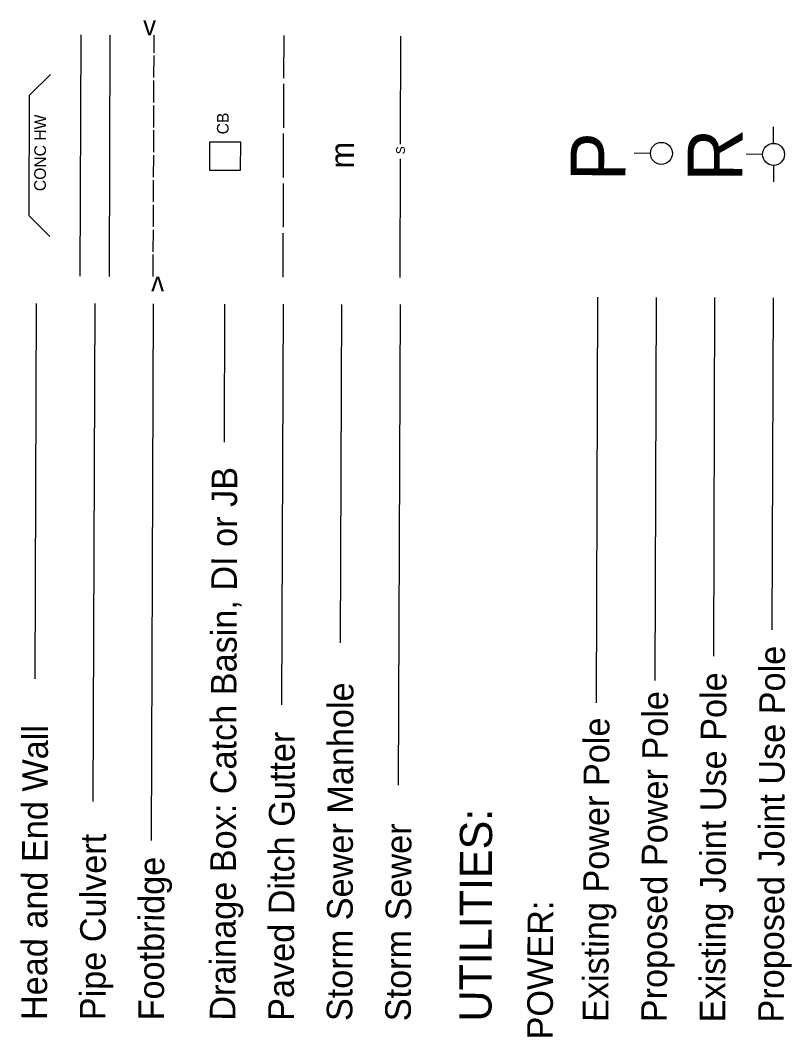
# Model space of a CAD drawing. Extents: x 2364794 to 2387902, y 795230 to 810426.
# Drawn here: x 2374608 to 2376455, y 805109 to 807541 of the extents above; entities that cross this region are included whole.
import ezdxf

# ---------------------------------------------------------------- set-up
doc = ezdxf.new("R2010")
doc.units = 0
doc.layers.add('Old_Level_5', color=7, linetype='Continuous')
doc.layers.add('Old_Level_63', color=7, linetype='Continuous')

# ---------------------------------------------------------------- blocks, each defined once
blk = doc.blocks.new('POLE')
at = {"layer": 'Old_Level_63'}
blk.add_line((0, 0.05), (0, 0.125), dxfattribs=at)
blk.add_circle((0, 0), 0.05, dxfattribs=at)
blk = doc.blocks.new('POLE4')
at = {"layer": 'Old_Level_63'}
for p, q in [((0, 0.0502), (0, 0.1252)), ((-0.05, 0.0002), (-0.125, 0.0002)), ((0.05, 0.0002), (0.125, 0.0002))]:
    blk.add_line(p, q, dxfattribs=at)
blk.add_circle((0, 0), 0.05, dxfattribs=at)

msp = doc.modelspace()

# ---------------------------------------------------------------- linework, layer by layer
at = {"layer": 'Old_Level_63'}
for p, q in [((2374751.3, 806928.4), (2374753.4, 807505.9)), ((2374821.3, 806928.1), (2374823.4, 807505.6)), ((2374928.2, 807463.2), (2374928.4, 807505.2)), ((2375239, 807402.6), (2375239.4, 807504.1)), ((2375518.5, 807244.3), (2375519.4, 807503.1)), ((2374928, 807403.7), (2374928.2, 807456.2)), ((2374630.4, 807361.9), (2374680.1, 807411.3)), ((2374927.8, 807344.2), (2374928, 807396.7)), ((2375238.6, 807283.6), (2375239, 807388.6)), ((2374629.3, 807073.2), (2374630.4, 807361.9)), ((2374927.6, 807284.7), (2374927.8, 807337.2)), ((2374927.4, 807225.2), (2374927.6, 807277.7)), ((2375238.2, 807164.6), (2375238.5, 807269.6)), ((2374927.2, 807165.7), (2374927.4, 807218.2)), ((2375517.3, 806925.7), (2375518.3, 807209.3)), ((2374927, 807106.2), (2374927.1, 807158.7)), ((2375237.8, 807045.6), (2375238.1, 807150.6)), ((2374926.7, 807046.7), (2374926.9, 807099.2)), ((2374678.7, 807023.5), (2374629.3, 807073.2)), ((2374926.5, 806987.2), (2374926.7, 807039.7)), ((2375237.3, 806926.6), (2375237.7, 807031.6)), ((2374926.3, 806927.7), (2374926.5, 806980.2)), ((2374646.1, 806863.6), (2374642.9, 805965.5)), ((2374786.1, 806863.1), (2374781.9, 805671.8)), ((2374926.1, 806862.6), (2374921.6, 805578.3)), ((2375097.1, 806862), (2375095.9, 806531.6)), ((2375237.1, 806861.5), (2375233.7, 805902.9)), ((2375377.1, 806861), (2375374.2, 806051.3)), ((2375517.1, 806860.6), (2375513, 805711.2)), ((2375990.3, 806878.4), (2375986.9, 805907.5)), ((2376130.3, 806877.9), (2376127, 805961.5)), ((2376270.3, 806877.4), (2376267.3, 806019.8)), ((2376410.3, 806876.9), (2376407.5, 806082.3))]:
    msp.add_line(p, q, dxfattribs=at)
msp.add_lwpolyline([(2375135.4, 807182.1), (2375135.7, 807249.4), (2375061.2, 807249.6), (2375061, 807182.3)], close=True, dxfattribs=at)

# ---------------------------------------------------------------- block references
at = {"layer": 'Old_Level_5', "xscale": 525, "yscale": 524.9999999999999, "rotation": 89.79761986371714}
for name, p in [('POLE4', (2376411.5, 807220)), ('POLE', (2376143, 807222.4))]:
    msp.add_blockref(name, p, dxfattribs=at)

# ---------------------------------------------------------------- texts
at = {"layer": 'Old_Level_63'}
for s, height, rotation, p in [('v', 46.2, 0.0385, (2374902.2, 807505.2)), ('CONC HW', 28, 89.7976, (2374669.2, 807132)), ('CB', 28, 89.7976, (2375106.8, 807267.9)), ('R', 131.2, 89.7976, (2376336.9, 807154.6)), ('P', 131.2, 89.7976, (2376056.9, 807155.6)), ('m', 57.7, 89.7976, (2375407.1, 807185.9)), ('S', 21, 89.7976, (2375528.9, 807220.5)), ('v', 46.2, 179.5568, (2374952.5, 806927.6)), ('Drainage Box: Catch Basin, DI or JB', 61.25, 89.7976, (2375122.8, 805147.3)), ('Proposed Joint Use Pole', 61.25, 89.7976, (2376435.9, 805142.7)), ('Existing Joint Use Pole', 61.25, 89.7976, (2376295.8, 805143.1)), ('Storm Sewer Manhole', 61.25, 89.7976, (2375402.9, 805146.3)), ('Proposed Power Pole', 61.25, 89.7976, (2376155.9, 805143.6)), ('Existing Power Pole', 61.25, 89.7976, (2376015.9, 805144.1)), ('Head and End Wall', 61.25, 89.7976, (2374671.9, 805148.8)), ('Paved Ditch Gutter', 61.25, 89.7976, (2375262.9, 805146.8)), ('UTILITIES:', 77, 89.7976, (2375736, 805145)), ('Storm Sewer', 61.25, 89.7976, (2375542.9, 805145.8)), ('Pipe Culvert', 61.25, 89.7976, (2374811.8, 805148.3)), ('Footbridge', 61.25, 89.7976, (2374951.8, 805147.9)), ('POWER:', 61.25, 89.7976, (2375882.8, 805102.3))]:
    msp.add_text(s, height=height, rotation=rotation, dxfattribs=at).set_placement(p)

doc.saveas('drawing.dxf')
